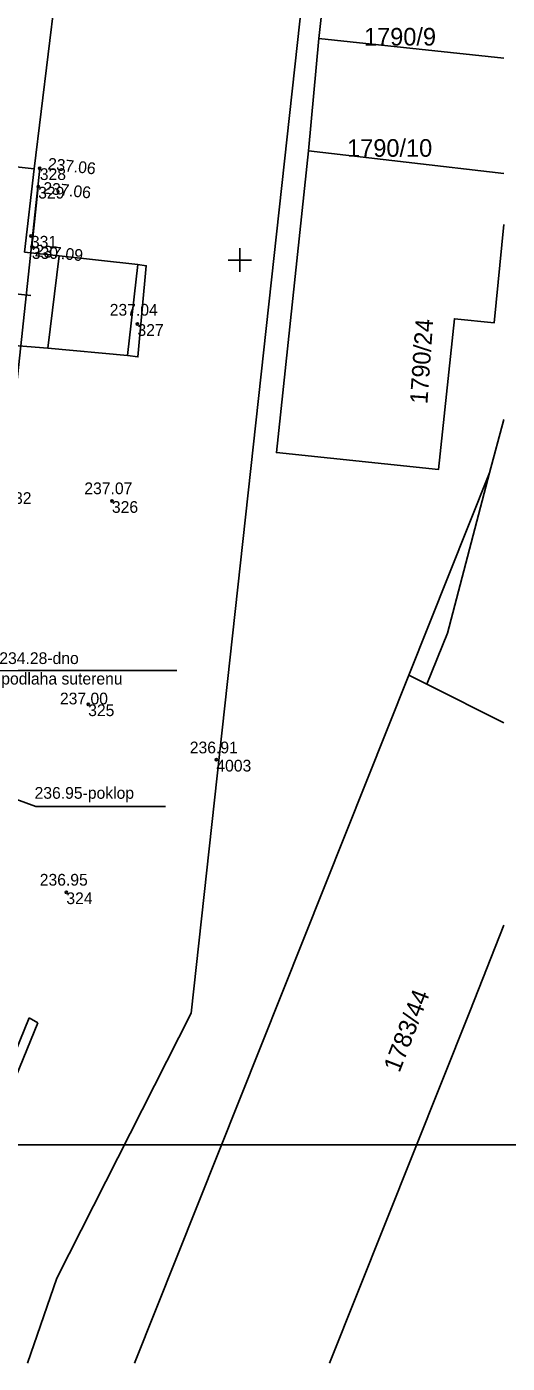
# Model space of a CAD drawing. Extents: x -596309 to -596099, y -1158697 to -1158513.
# Drawn here: x -596209.1 to -596188.6, y -1158697 to -1158640.1 of the extents above; entities that cross this region are included whole.
import ezdxf

# ---------------------------------------------------------------- set-up
doc = ezdxf.new("R2010")
doc.units = 0
for name, color, linetype in [('Pop  PČ popisy', 7, 'Continuous'), ('Vrstva 1', 7, 'Continuous'), ('Vrstva 14', 7, 'Continuous'), ('Vrstva 2', 7, 'Continuous'), ('Vrstva 3', 7, 'Continuous'), ('Vrstva 5', 7, 'Continuous'), ('Vrstva 59', 7, 'Continuous'), ('Vrstva 6', 7, 'Continuous'), ('Vrstva 61', 7, 'Continuous'), ('Vrstva 63', 7, 'Continuous')]:
    doc.layers.add(name, color=color, linetype=linetype)

msp = doc.modelspace()

# ---------------------------------------------------------------- linework, layer by layer
at = {"layer": 'Pop  PČ popisy'}
msp.add_line((-596208.91, -1158651.51), (-596210.91, -1158651.3), dxfattribs=at)
at = {"layer": 'Vrstva 1'}
for p, q in [((-596192.08, -1158590.8), (-596202.08, -1158682.08)), ((-596196.64, -1158640.56), (-596196.12, -1158635.98)), ((-596207.77, -1158638.04), (-596208.76, -1158646.12)), ((-596197.08, -1158645.35), (-596196.64, -1158640.56)), ((-596196.64, -1158640.56), (-596188.76, -1158641.398)), ((-596197.08, -1158645.35), (-596188.76, -1158646.316)), ((-596207.7, -1158649.82), (-596208.18, -1158653.75)), ((-596204.34, -1158650.19), (-596204.79, -1158654.07)), ((-596191.16, -1158665.89), (-596189.36, -1158659.06)), ((-596192.03, -1158668.07), (-596191.16, -1158665.89)), ((-596204.48, -1158697), (-596192.8, -1158667.68)), ((-596192.8, -1158667.68), (-596192.03, -1158668.07)), ((-596192.03, -1158668.07), (-596188.76, -1158669.71)), ((-596215.007, -1158697), (-596208.97, -1158682.29)), ((-596208.97, -1158682.29), (-596208.61, -1158682.49)), ((-596202.08, -1158682.08), (-596207.8, -1158693.37)), ((-596208.61, -1158682.49), (-596214.526, -1158697)), ((-596207.8, -1158693.37), (-596209.05, -1158697))]:
    msp.add_line(p, q, dxfattribs=at)
for points in [[(-596209.17, -1158649.66), (-596208.76, -1158646.12), (-596214.51, -1158645.47), (-596207.66, -1158581.2), (-596207, -1158581.28)], [(-596188.76, -1158648.487), (-596189.17, -1158652.68), (-596190.86, -1158652.5), (-596191.54, -1158658.93), (-596198.44, -1158658.2), (-596197.08, -1158645.35)], [(-596209.78, -1158653.62), (-596208.18, -1158653.75), (-596204.79, -1158654.07), (-596204.34, -1158654.13), (-596203.99, -1158650.24), (-596204.34, -1158650.19), (-596207.7, -1158649.82), (-596209.17, -1158649.66)], [(-596192.8, -1158667.68), (-596189.36, -1158659.06), (-596188.76, -1158656.787)], [(-596188.76, -1158678.341), (-596190.2, -1158682.01), (-596196.176, -1158697)]]:
    msp.add_lwpolyline(points, dxfattribs=at)
at = {"layer": 'Vrstva 2'}
for points in [[(-596202.68, -1158667.481), (-596210.261, -1158667.481), (-596215.74, -1158665.39)], [(-596203.163, -1158673.276), (-596208.688, -1158673.276), (-596210.678, -1158672.56)]]:
    msp.add_lwpolyline(points, dxfattribs=at)
for centre in [(-596208.52, -1158646.09), (-596208.59, -1158646.88), (-596208.9, -1158648.97), (-596208.86, -1158649.45), (-596204.36, -1158652.73), (-596205.45, -1158660.27), (-596206.46, -1158668.93), (-596201, -1158671.29), (-596207.39, -1158676.94)]:
    msp.add_circle(centre, 0.05, dxfattribs=at)
at = {"layer": 'Vrstva 3'}
for p, q in [((-596208.52, -1158646.09), (-596208.519, -1158646.09)), ((-596208.59, -1158646.88), (-596208.589, -1158646.88)), ((-596208.9, -1158648.97), (-596208.899, -1158648.97)), ((-596208.86, -1158649.45), (-596208.859, -1158649.45)), ((-596204.36, -1158652.73), (-596204.359, -1158652.73)), ((-596205.45, -1158660.27), (-596205.449, -1158660.27)), ((-596206.46, -1158668.93), (-596206.459, -1158668.93)), ((-596201, -1158671.29), (-596200.999, -1158671.29)), ((-596207.39, -1158676.94), (-596207.389, -1158676.94))]:
    msp.add_line(p, q, dxfattribs=at)
at = {"layer": 'Vrstva 5'}
msp.add_line((-596208.52, -1158646.09), (-596209.99, -1158659.89), dxfattribs=at)
at = {"layer": 'Vrstva 6'}
msp.add_line((-596208.86, -1158649.45), (-596208.59, -1158646.88), dxfattribs=at)
at = {"layer": 'Vrstva 61'}
for p, q in [((-596200.5, -1158650), (-596199.5, -1158650)), ((-596200, -1158649.5), (-596200, -1158650.5))]:
    msp.add_line(p, q, dxfattribs=at)
at = {"layer": 'Vrstva 63'}
msp.add_lwpolyline([(-596309.058, -1158687.689), (-596099.058, -1158687.689), (-596099.058, -1158539.189), (-596309.058, -1158539.189)], close=True, dxfattribs=at)

# ---------------------------------------------------------------- texts
at = {"layer": 'Vrstva 14'}
for s, p in [('1790/9', (-596194.71, -1158640.86)), ('1790/10', (-596195.43, -1158645.6))]:
    msp.add_text(s, height=0.75, dxfattribs=at).set_placement(p)
for s, rotation, p in [('1790/24', 86, (-596192.012, -1158656.149)), ('1783/44', 69, (-596193.202, -1158684.65))]:
    msp.add_text(s, height=0.75, rotation=rotation, dxfattribs=at).set_placement(p)
at = {"layer": 'Vrstva 2'}
for s, p in [('237.06', (-596208.202, -1158646.137)), ('237.06', (-596208.404, -1158647.162)), ('237.09', (-596208.745, -1158649.835))]:
    msp.add_text(s, height=0.5, rotation=353.9197, dxfattribs=at).set_placement(p)
for s, p in [('237.04', (-596205.542, -1158652.369)), ('237.07', (-596206.624, -1158659.975)), ('234.28-dno', (-596210.246, -1158667.21)), ('podlaha suterenu', (-596210.163, -1158668.083)), ('237.00', (-596207.664, -1158668.93)), ('236.91', (-596202.132, -1158671.016)), ('236.95-poklop', (-596208.743, -1158672.951)), ('236.95', (-596208.523, -1158676.651))]:
    msp.add_text(s, height=0.5, dxfattribs=at).set_placement(p)
at = {"layer": 'Vrstva 59'}
for s, p in [('328', (-596208.52, -1158646.59)), ('329', (-596208.59, -1158647.38)), ('331', (-596208.9, -1158649.47)), ('330', (-596208.86, -1158649.95)), ('327', (-596204.36, -1158653.23)), ('332', (-596209.99, -1158660.39)), ('326', (-596205.45, -1158660.77)), ('325', (-596206.46, -1158669.43)), ('4003', (-596201, -1158671.79)), ('324', (-596207.39, -1158677.44))]:
    msp.add_text(s, height=0.5, dxfattribs=at).set_placement(p)

doc.saveas('drawing.dxf')
